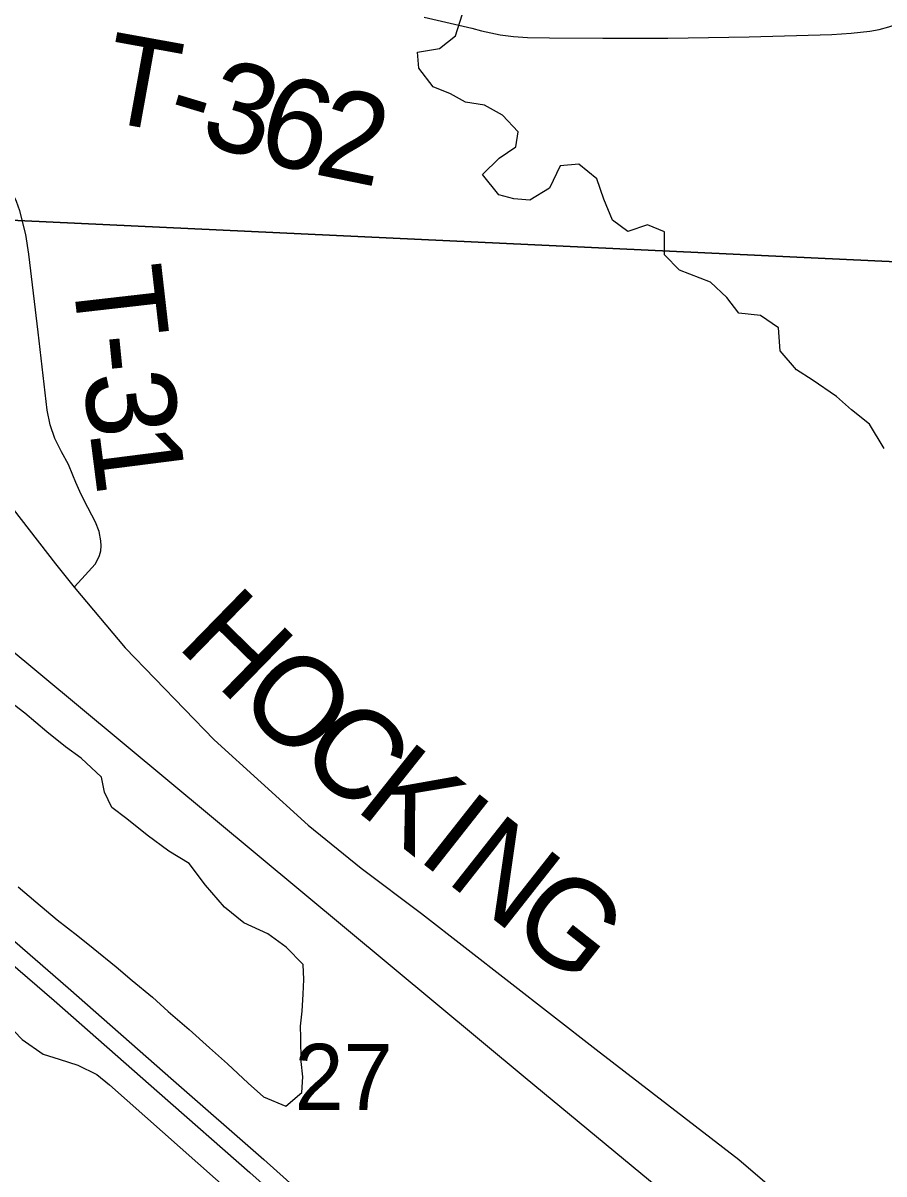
# Model space of a CAD drawing. Extents: x 39.8 to 73.8, y 13 to 35.
# Drawn here: x 44.694 to 45.24, y 30.521 to 31.251 of the extents above; entities that cross this region are included whole.
import ezdxf

# ---------------------------------------------------------------- set-up
doc = ezdxf.new("R2010")
doc.units = 0
for name, color, linetype in [('GM_X_Corporation', 7, 'Continuous'), ('GM_X_County_Road', 7, 'Continuous'), ('GM_X_County_Road_Text', 7, 'Continuous'), ('GM_X_Minor_Lake', 7, 'Continuous'), ('GM_X_Minor_River', 7, 'Continuous'), ('GM_X_Rail_Line', 7, 'Continuous'), ('GM_X_Section_Text', 7, 'Continuous'), ('GM_X_Township_Road', 7, 'Continuous'), ('GM_X_Township_Road_Text', 7, 'Continuous'), ('GM_X_US_Route', 7, 'Continuous')]:
    doc.layers.add(name, color=color, linetype=linetype)

msp = doc.modelspace()

# ---------------------------------------------------------------- linework, layer by layer
at = {"layer": 'GM_X_Corporation'}
for points in [[(44.51605, 32.19572), (45.50689, 32.1262), (45.43139, 31.091), (44.4392, 31.1377)], [(45.43139, 31.091), (45.35678, 30.04923), (44.36734, 30.10866), (44.4392, 31.1377)]]:
    msp.add_lwpolyline(points, close=True, dxfattribs=at)
at = {"layer": 'GM_X_County_Road'}
for points in [[(44.44218, 31.25711), (44.48765, 31.1981), (44.54613, 31.12252), (44.65928, 30.97939), (44.71463, 30.90824), (44.72644, 30.89333), (44.75886, 30.855), (44.81526, 30.79658), (44.87483, 30.74254), (44.90837, 30.71525), (44.94666, 30.68662), (45.0573, 30.60034), (45.14776, 30.53069), (45.1864, 30.49736), (45.21018, 30.47485), (45.25625, 30.41816)], [(44.61064, 30.68328), (44.67255, 30.62834), (44.69344, 30.6067), (44.7068, 30.59748), (44.71696, 30.59428), (44.72881, 30.59033), (44.74085, 30.5845), (44.74894, 30.57791), (44.87201, 30.46877), (44.92544, 30.41816), (44.95724, 30.38297), (44.98791, 30.34666), (45.02367, 30.29961), (45.05979, 30.24561), (45.07504, 30.22002), (45.10608, 30.1647), (45.11907, 30.13967), (45.18154, 30.00363), (45.19396, 29.97672), (45.2075, 29.95264), (45.22124, 29.9342), (45.23479, 29.91726), (45.25379, 29.89788)]]:
    msp.add_lwpolyline(points, dxfattribs=at)
at = {"layer": 'GM_X_Minor_Lake'}
for p, q in [((44.69518, 30.81346), (44.68264, 30.82328)), ((44.70924, 30.80174), (44.69518, 30.81346)), ((44.72102, 30.7923), (44.70924, 30.80174)), ((44.73089, 30.78512), (44.72102, 30.7923)), ((44.74382, 30.77302), (44.73089, 30.78512)), ((44.74575, 30.76354), (44.74382, 30.77302)), ((44.75034, 30.7537), (44.74575, 30.76354)), ((44.75983, 30.74652), (44.75034, 30.7537)), ((44.77275, 30.73632), (44.75983, 30.74652)), ((44.78643, 30.72612), (44.77275, 30.73632)), ((44.79934, 30.71819), (44.78643, 30.72612)), ((44.80962, 30.70457), (44.79934, 30.71819)), ((44.69111, 30.70343), (44.70213, 30.69399)), ((44.8218, 30.69057), (44.80962, 30.70457)), ((44.70213, 30.69399), (44.71581, 30.68265)), ((44.83396, 30.68074), (44.8218, 30.69057)), ((44.71581, 30.68265), (44.72872, 30.67245)), ((44.84913, 30.67358), (44.83396, 30.68074)), ((44.86091, 30.66528), (44.84913, 30.67358)), ((44.72872, 30.67245), (44.73861, 30.66451)), ((44.87156, 30.65431), (44.86091, 30.66528)), ((44.73861, 30.66451), (44.75304, 30.6528)), ((44.75304, 30.6528), (44.76331, 30.6441)), ((44.87197, 30.64483), (44.87156, 30.65431)), ((44.76331, 30.6441), (44.77622, 30.63352)), ((44.87164, 30.63534), (44.87197, 30.64483)), ((44.77622, 30.63352), (44.78611, 30.62445)), ((44.87093, 30.62472), (44.87164, 30.63534)), ((44.78611, 30.62445), (44.79941, 30.61311)), ((44.86983, 30.61523), (44.87093, 30.62472)), ((44.87014, 30.60801), (44.86983, 30.61523)), ((44.79941, 30.61311), (44.81234, 30.60139)), ((44.8703, 30.59285), (44.87014, 30.60801)), ((44.81234, 30.60139), (44.82374, 30.59119)), ((44.87148, 30.58299), (44.8703, 30.59285)), ((44.82374, 30.59119), (44.83666, 30.57909)), ((44.83666, 30.57909), (44.84655, 30.5704)), ((44.87077, 30.57313), (44.87148, 30.58299)), ((44.84655, 30.5704), (44.86058, 30.56437)), ((44.86058, 30.56437), (44.87077, 30.57313))]:
    msp.add_line(p, q, dxfattribs=at)
at = {"layer": 'GM_X_Minor_River'}
for points in [[(45.0064, 31.17254), (45.00787, 31.18202), (44.99798, 31.19262), (44.9866, 31.19903), (44.97447, 31.20089), (44.96498, 31.20617), (44.95398, 31.21068), (44.94484, 31.22242), (44.94404, 31.23266), (44.95804, 31.23498), (44.96823, 31.24297), (44.97234, 31.25626)], [(45.23972, 30.98132), (45.23056, 30.99685), (45.21916, 31.00592), (45.20966, 31.01423), (45.19409, 31.0248), (45.18422, 31.03122), (45.17394, 31.04333), (45.17274, 31.05774), (45.16135, 31.06567), (45.14771, 31.06714), (45.1401, 31.07698), (45.12983, 31.08681), (45.11011, 31.09434), (45.1006, 31.10417), (45.10054, 31.11859), (45.08992, 31.12311), (45.07744, 31.11889), (45.06756, 31.12607), (45.06221, 31.13933), (45.05761, 31.15221), (45.04621, 31.16166), (45.03447, 31.16049), (45.02772, 31.14643), (45.01526, 31.1388), (45.00503, 31.13953), (44.99555, 31.14215), (44.98527, 31.15502), (44.99583, 31.16529), (45.0064, 31.17254)]]:
    msp.add_lwpolyline(points, dxfattribs=at)
at = {"layer": 'GM_X_Rail_Line'}
msp.add_lwpolyline([(44.56709, 30.95303), (44.72923, 30.81819), (45.01239, 30.58254), (45.10261, 30.50771), (45.19874, 30.42629), (45.20767, 30.41715), (45.22004, 30.40444), (45.2312, 30.39228), (45.24112, 30.38102), (45.26421, 30.3518), (45.57407, 29.92138), (45.66857, 29.79002), (45.71154, 29.73068), (45.7298, 29.70543), (45.75397, 29.67535), (45.79399, 29.62916), (45.86863, 29.54493), (45.96233, 29.44021), (46.06621, 29.3238)], dxfattribs=at)
at = {"layer": 'GM_X_Township_Road'}
for points in [[(44.94831, 31.2548), (44.97853, 31.24772), (44.98455, 31.24617), (44.99652, 31.24359), (45.00489, 31.24245), (45.01379, 31.24196), (45.02762, 31.2416), (45.06149, 31.24147), (45.10263, 31.24149), (45.15421, 31.24226), (45.20664, 31.2438), (45.21878, 31.24456), (45.2307, 31.24593), (45.23671, 31.24702), (45.24267, 31.24856), (45.25139, 31.25156)], [(44.72566, 30.96451), (44.72296, 30.97121), (44.7185, 30.97932), (44.71422, 30.98762), (44.71118, 30.99643), (44.70929, 31.00558), (44.70367, 31.05508), (44.69784, 31.10455), (44.69582, 31.11694), (44.69203, 31.13208), (44.68994, 31.138), (44.68584, 31.14642), (44.68094, 31.15438), (44.67531, 31.16184), (44.66885, 31.16849), (44.66165, 31.17414), (44.65358, 31.17884), (44.64204, 31.18353), (44.62714, 31.18805), (44.56456, 31.20392), (44.54891, 31.20831)], [(44.72644, 30.89333), (44.73137, 30.89879), (44.73972, 30.90803), (44.74138, 30.91065), (44.74259, 30.9135), (44.7433, 30.91651), (44.74359, 30.9196), (44.74349, 30.9227), (44.74229, 30.92881), (44.74008, 30.93465), (44.73277, 30.94841), (44.73016, 30.95407), (44.72759, 30.95973), (44.72566, 30.96451)]]:
    msp.add_lwpolyline(points, dxfattribs=at)
at = {"layer": 'GM_X_US_Route'}
for points in [[(44.05154, 31.2294), (44.05875, 31.22309), (44.10958, 31.17852), (44.16846, 31.1264), (44.20614, 31.09396), (44.28144, 31.02734), (44.33741, 30.97832), (44.40419, 30.91943), (44.4792, 30.85396), (44.55027, 30.7908), (44.60833, 30.7398), (44.64058, 30.712), (44.68894, 30.66874), (44.72266, 30.63946), (44.78944, 30.58074), (44.84669, 30.53056), (44.8837, 30.4975)], [(44.14234, 31.13348), (44.15951, 31.11828), (44.16084, 31.11713), (44.19719, 31.08584), (44.27253, 31.01924), (44.32849, 30.97023), (44.39528, 30.91134), (44.47029, 30.84587), (44.54135, 30.7827), (44.59942, 30.73171), (44.63166, 30.70391), (44.68002, 30.66065), (44.71374, 30.63137), (44.78053, 30.57264), (44.83777, 30.52247), (44.87479, 30.48941)]]:
    msp.add_lwpolyline(points, dxfattribs=at)

# ---------------------------------------------------------------- texts
at = {"layer": 'GM_X_County_Road_Text'}
for s, rotation, p in [('H', 315.71349, (44.79057, 30.85626)), ('O', 317.37957, (44.82767, 30.82011)), ('C', 319.54272, (44.86622, 30.7847)), ('K', 321.5496, (44.9034, 30.75304)), ('I', 321.76796, (44.94274, 30.7218)), ('N', 321.76176, (44.96107, 30.70736)), ('G', 321.76425, (45.00035, 30.67641))]:
    msp.add_text(s, height=0.05682, rotation=rotation, dxfattribs=at).set_placement(p)
at = {"layer": 'GM_X_Section_Text'}
msp.add_text('27', height=0.041856, rotation=0.00001, dxfattribs=at).set_placement((44.86612, 30.56207))
at = {"layer": 'GM_X_Township_Road_Text'}
for s, rotation, p in [('T', 349.76262, (44.74199, 31.18963)), ('3', 343.25613, (44.80454, 31.17571)), ('6', 345.55703, (44.84045, 31.16496)), ('-', 343.19458, (44.78214, 31.18247)), ('2', 348.4257, (44.87737, 31.15553)), ('T', 276.52304, (44.725, 31.09382)), ('-', 275.71359, (44.7298, 31.05189)), ('3', 276.40942, (44.73218, 31.02813)), ('1', 277.27552, (44.73616, 30.99269))]:
    msp.add_text(s, height=0.05682, rotation=rotation, dxfattribs=at).set_placement(p)

doc.saveas('drawing.dxf')
